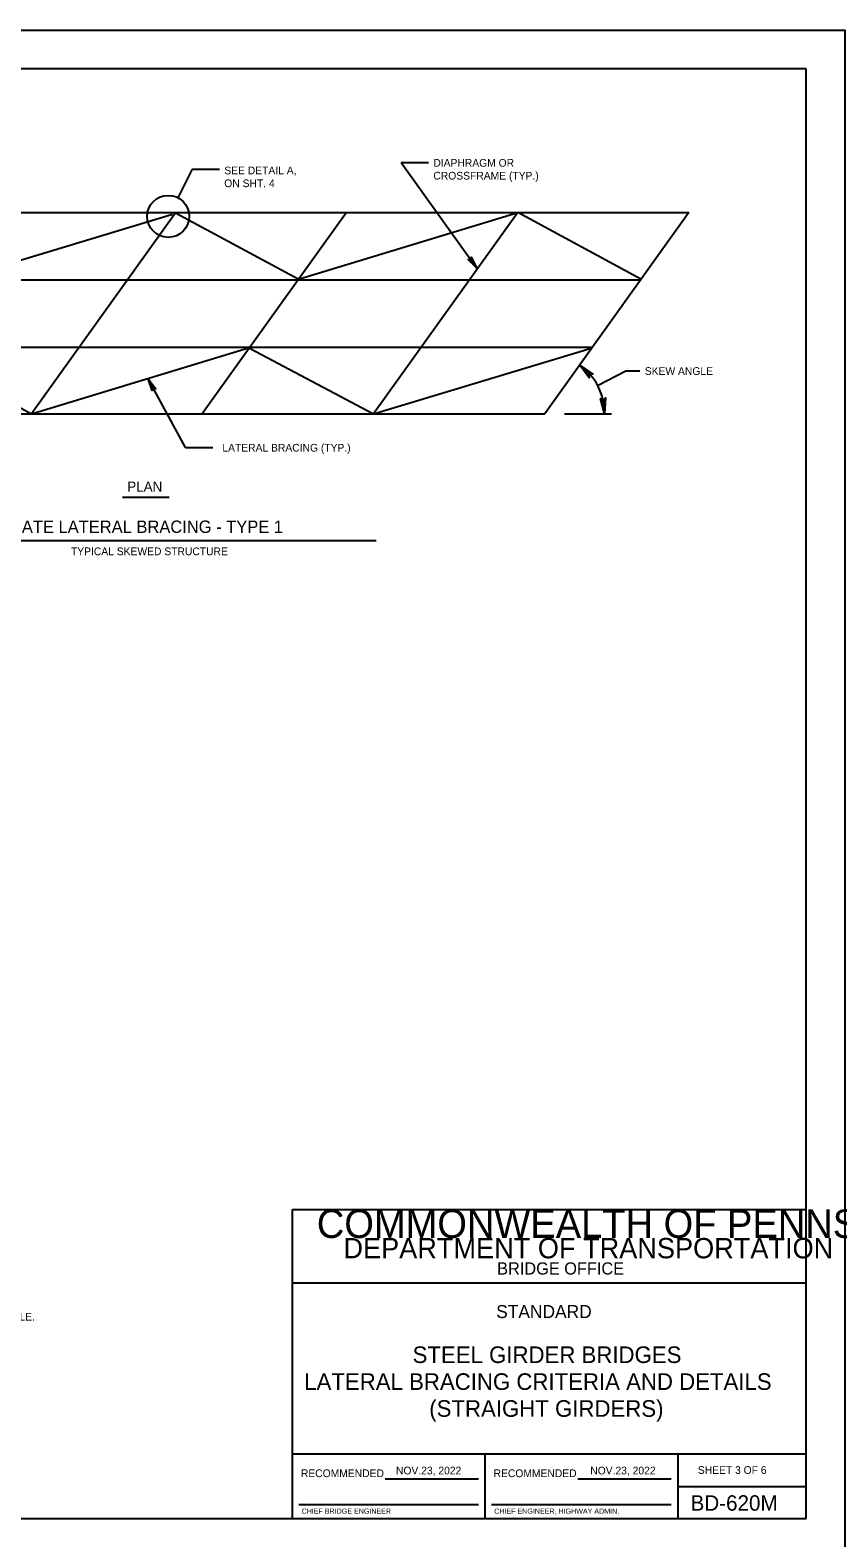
# Model space of a CAD drawing. Extents: x 30 to 2621, y -33 to 1155.
# Drawn here: x 1395 to 1710, y 569 to 1155 of the extents above; entities that cross this region are included whole.
import ezdxf

# ---------------------------------------------------------------- set-up
doc = ezdxf.new("R2010")
doc.units = 0
for name, color, linetype in [('1', 7, 'Continuous'), ('2', 7, 'Continuous'), ('PLT-BNDY', 7, 'Continuous'), ('SIGNATORY TITLES', 7, 'Continuous')]:
    doc.layers.add(name, color=color, linetype=linetype)

msp = doc.modelspace()

# ---------------------------------------------------------------- linework, layer by layer
at = {"layer": '1'}
for p, q in [((1697.5, 1140), (911.5, 1140)), ((1697.5, 576), (1697.5, 1140)), ((1539.83, 1103.48), (1550.44, 1103.48)), ((1539.83, 1103.48), (1569.3, 1062.35)), ((1458.53, 1100.87), (1452.92, 1089.83)), ((1458.53, 1100.87), (1469.14, 1100.87)), ((1366.36, 1057.92), (1450.85, 1083.42)), ((1385.13, 1084.13), (1651.89, 1084.13)), ((1452.1, 1084.13), (1396.01, 1005.8)), ((1404.25, 1084.13), (1404.25, 1084.13)), ((1499.77, 1058.07), (1452.05, 1083.75)), ((1518.55, 1084.13), (1462.46, 1005.8)), ((1499.9, 1058.07), (1585.22, 1084.13)), ((1585.22, 1084.13), (1529.13, 1005.8)), ((1633.11, 1058.13), (1585.22, 1084.13)), ((1651.89, 1084.13), (1595.8, 1005.8)), ((1366.36, 1057.92), (1633.12, 1057.92)), ((1347.59, 1031.7), (1614.35, 1031.7)), ((1347.59, 1031.7), (1396.01, 1005.8)), ((1396.01, 1005.8), (1480.49, 1031.38)), ((1481.02, 1031.2), (1529.13, 1005.8)), ((1529.13, 1005.8), (1613.84, 1031.25)), ((1616.34, 1016.71), (1627.29, 1022.53)), ((1627.29, 1022.53), (1632.74, 1022.53)), ((1455.92, 992.66), (1441.38, 1019.34)), ((1329.04, 1005.8), (1595.8, 1005.8)), ((1603.47, 1005.8), (1621.75, 1005.8)), ((1455.92, 992.66), (1466.53, 992.66)), ((1431.44, 973.31), (1449.53, 973.31)), ((1365.18, 956.48), (1530.19, 956.48)), ((1497.5, 576), (1497.5, 696.23)), ((1497.5, 696.23), (1697.5, 696.23)), ((1497.5, 667.75), (1697.5, 667.75)), ((1697.5, 601), (1497.5, 601)), ((1572.5, 576), (1572.5, 601)), ((1647.5, 601), (1647.5, 576)), ((1533.59, 591.5), (1570, 591.5)), ((1608.59, 591.5), (1645, 591.5)), ((1647.5, 588.5), (1697.5, 588.5)), ((1500, 581.5), (1570, 581.5)), ((1575, 581.5), (1645, 581.5)), ((911.5, 576), (1697.5, 576))]:
    msp.add_line(p, q, dxfattribs=at)
for points in [[(1567.12, 1066.37), (1566.95, 1066.04), (1569.3, 1062.35), (1567.12, 1066.37), (1567.14, 1066.67), (1569.3, 1062.35), (1566.58, 1065.77), (1566.22, 1065.71), (1569.3, 1062.35), (1565.9, 1065.78), (1566.22, 1065.71)], [(1613.03, 1020.17), (1613.17, 1020.63), (1609.34, 1024.71), (1613.03, 1020.17), (1613.07, 1019.78), (1609.34, 1024.71), (1613.57, 1021.05), (1614, 1021.21), (1609.34, 1024.71), (1614.42, 1021.19), (1614, 1021.21)], [(1443.05, 1015.08), (1443.26, 1015.39), (1441.38, 1019.34), (1443.05, 1015.08), (1442.99, 1014.78), (1441.38, 1019.34), (1443.66, 1015.61), (1444.02, 1015.62), (1441.38, 1019.34), (1444.33, 1015.51), (1444.02, 1015.62)], [(1619.14, 1011.64), (1618.75, 1011.38), (1619.06, 1005.8), (1619.14, 1011.64), (1619.36, 1011.96), (1619.06, 1005.8), (1618.17, 1011.31), (1617.73, 1011.47), (1619.06, 1005.8), (1617.42, 1011.75), (1617.73, 1011.47)]]:
    msp.add_lwpolyline(points, dxfattribs=at)
msp.add_circle((1449.19, 1082.57), 8.17, dxfattribs=at)
msp.add_arc((1595.8, 1005.8), 23.26, 0, 54.39724, dxfattribs=at)
at = {"layer": '2'}
msp.add_line((1697.5, 601), (1497.5, 601), dxfattribs=at)
at = {"layer": 'PLT-BNDY'}
msp.add_lwpolyline([(871.5, 1155), (1712.5, 1155), (1712.5, 561), (871.5, 561)], close=True, dxfattribs=at)

# ---------------------------------------------------------------- texts
at = {"layer": '1'}
for s, height, p in [('DIAPHRAGM OR', 3, (1552.39, 1101.88)), ('SEE DETAIL A,', 3, (1471.01, 1098.92)), ('ON SHT. 4', 3, (1471.01, 1093.92)), ('CROSSFRAME (TYP.)', 3, (1552.39, 1096.88)), ('SKEW ANGLE', 3, (1634.69, 1020.89)), ('LATERAL BRACING (TYP.)', 3, (1470.26, 991.05)), ('PLAN', 3.9, (1433.25, 975.48)), ('ALTERNATE LATERAL BRACING - TYPE 1', 4.8, (1366.9, 959.43)), ('TYPICAL SKEWED STRUCTURE', 3, (1411.33, 950.75)), ('COMMONWEALTH OF PENNSYLVANIA', 11.0789, (1507.03, 685.15)), ('COMMONWEALTH OF PENNSYLVANIA', 11.0789, (1507.03, 685.15)), ('DEPARTMENT OF TRANSPORTATION', 7.8962, (1517.38, 677.25)), ('DEPARTMENT OF TRANSPORTATION', 7.8962, (1517.38, 677.25)), ('BRIDGE OFFICE', 4.7495, (1577.22, 670.92)), ('STANDARD', 5.055, (1576.84, 654)), ('2. USE ANGLE OR STRUCTURAL TEE BRACING MEMBERS WHENEVER POSSIBLE.', 3, (1238.57, 653.01)), ('STEEL GIRDER BRIDGES', 6.4601, (1544.31, 636.51)), ('LATERAL BRACING CRITERIA AND DETAILS', 6.4601, (1502.13, 626.05)), ('(STRAIGHT GIRDERS)', 6.4601, (1550.79, 615.59)), ('RECOMMENDED', 3, (1500.83, 592.12)), ('RECOMMENDED', 3, (1575.83, 592.12)), ('SHEET 3 OF 6', 3, (1655.33, 593.38)), ('BD-620M', 6, (1652.5, 579.06))]:
    msp.add_text(s, height=height, dxfattribs=at).set_placement(p)
at = {"layer": 'SIGNATORY TITLES'}
for s, height, p in [('NOV.23, 2022', 3, (1537.84, 593.18)), ('NOV.23, 2022', 3, (1613.46, 593.18)), ('CHIEF BRIDGE ENGINEER', 2, (1501.09, 577.88)), ('CHIEF ENGINEER, HIGHWAY ADMIN.', 2, (1576.09, 577.88))]:
    msp.add_text(s, height=height, dxfattribs=at).set_placement(p)

doc.saveas('drawing.dxf')
